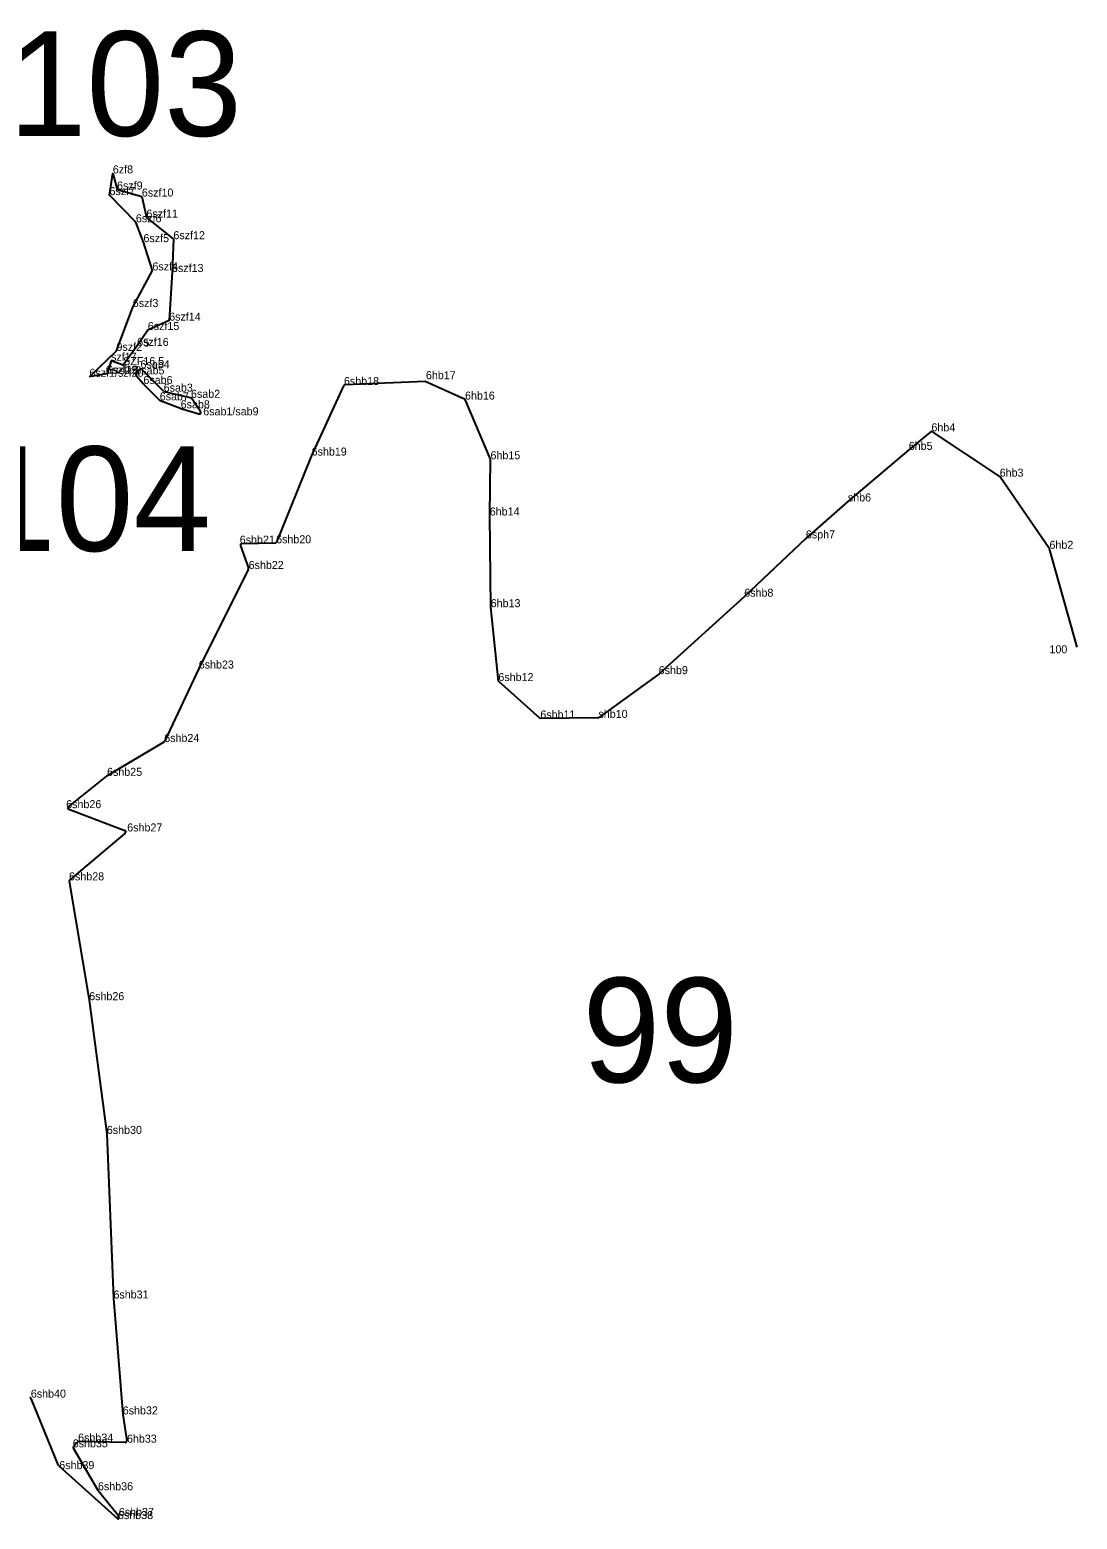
# Model space of a CAD drawing. Extents: x 2072529 to 2268812, y 436423 to 470008.
# Drawn here: x 2138755 to 2139410, y 443063 to 443993 of the extents above; entities that cross this region are included whole.
import ezdxf

# ---------------------------------------------------------------- set-up
doc = ezdxf.new("R2010")
doc.units = 0
for name, color, linetype in [('Old_Level_10', 7, 'Continuous'), ('Old_Level_20', 7, 'Continuous'), ('Old_Level_60', 7, 'Continuous'), ('Old_Level_62', 7, 'Continuous')]:
    doc.layers.add(name, color=color, linetype=linetype)

msp = doc.modelspace()

# ---------------------------------------------------------------- linework, layer by layer
at = {"layer": 'Old_Level_10'}
for p, q in [((2138823.896, 443781.131), (2138821.883, 443778.794)), ((2138838.864, 443767.558), (2138825.364, 443781.182)), ((2138821.875, 443777.498), (2138826.367, 443772.158)), ((2138826.425, 443772.095), (2138836.453, 443762.059)), ((2138951.494, 443770.917), (2138931.546, 443727.436)), ((2138951.494, 443770.917), (2138931.546, 443727.436)), ((2138951.494, 443770.917), (2138931.546, 443727.436)), ((2139002.527, 443773.731), (2138952.359, 443771.499)), ((2139002.527, 443773.731), (2138952.359, 443771.499)), ((2139002.527, 443773.731), (2138952.359, 443771.499)), ((2138836.804, 443761.831), (2138849.667, 443756.932)), ((2138855.768, 443763.565), (2138839.353, 443767.287)), ((2138862.122, 443754.921), (2138856.366, 443763.162)), ((2138849.725, 443756.912), (2138861.004, 443753.394)), ((2138931.529, 443727.395), (2138909.575, 443673.234)), ((2138931.529, 443727.395), (2138909.575, 443673.234)), ((2138931.529, 443727.395), (2138909.575, 443673.234)), ((2138887.055, 443671.027), (2138892.018, 443656.954)), ((2138887.055, 443671.027), (2138892.018, 443656.954)), ((2138887.055, 443671.027), (2138892.018, 443656.954)), ((2138908.66, 443672.61), (2138887.986, 443672.36)), ((2138908.66, 443672.61), (2138887.986, 443672.36)), ((2138908.66, 443672.61), (2138887.986, 443672.36)), ((2138891.969, 443656.173), (2138861.016, 443594.36)), ((2138891.969, 443656.173), (2138861.016, 443594.36)), ((2138891.969, 443656.173), (2138861.016, 443594.36)), ((2138861.006, 443594.338), (2138839.528, 443548.761)), ((2138861.006, 443594.338), (2138839.528, 443548.761)), ((2138861.006, 443594.338), (2138839.528, 443548.761)), ((2138839.133, 443548.327), (2138803.723, 443527.353)), ((2138839.133, 443548.327), (2138803.723, 443527.353)), ((2138839.133, 443548.327), (2138803.723, 443527.353)), ((2138803.612, 443527.277), (2138779.509, 443508.203)), ((2138803.612, 443527.277), (2138779.509, 443508.203)), ((2138803.612, 443527.277), (2138779.509, 443508.203)), ((2138779.774, 443506.484), (2138814.695, 443493.167)), ((2138779.774, 443506.484), (2138814.695, 443493.167)), ((2138779.774, 443506.484), (2138814.695, 443493.167)), ((2138814.982, 443491.467), (2138780.361, 443462.361)), ((2138814.982, 443491.467), (2138780.361, 443462.361)), ((2138814.982, 443491.467), (2138780.361, 443462.361)), ((2138780.019, 443461.429), (2138792.508, 443387.166)), ((2138780.019, 443461.429), (2138792.508, 443387.166)), ((2138780.019, 443461.429), (2138792.508, 443387.166)), ((2138792.513, 443387.131), (2138803.533, 443303.65)), ((2138792.513, 443387.131), (2138803.533, 443303.65)), ((2138792.513, 443387.131), (2138803.533, 443303.65)), ((2138803.541, 443303.56), (2138807.688, 443200.784)), ((2138803.541, 443303.56), (2138807.688, 443200.784)), ((2138803.541, 443303.56), (2138807.688, 443200.784)), ((2138807.691, 443200.744), (2138813.489, 443128.377)), ((2138807.691, 443200.744), (2138813.489, 443128.377)), ((2138807.691, 443200.744), (2138813.489, 443128.377)), ((2138773.409, 443096.375), (2138756.294, 443138.223)), ((2138773.409, 443096.375), (2138756.294, 443138.223)), ((2138773.409, 443096.375), (2138756.294, 443138.223)), ((2138813.497, 443128.309), (2138815.947, 443111.862)), ((2138813.497, 443128.309), (2138815.947, 443111.862)), ((2138813.497, 443128.309), (2138815.947, 443111.862)), ((2138785.286, 443111.026), (2138782.751, 443108.342)), ((2138785.286, 443111.026), (2138782.751, 443108.342)), ((2138785.286, 443111.026), (2138782.751, 443108.342)), ((2138814.937, 443110.715), (2138786.035, 443111.339)), ((2138814.937, 443110.715), (2138786.035, 443111.339)), ((2138814.937, 443110.715), (2138786.035, 443111.339)), ((2138782.616, 443107.149), (2138797.969, 443081.018)), ((2138782.616, 443107.149), (2138797.969, 443081.018)), ((2138782.616, 443107.149), (2138797.969, 443081.018)), ((2138798.055, 443080.894), (2138810.724, 443065.303)), ((2138798.055, 443080.894), (2138810.724, 443065.303)), ((2138798.055, 443080.894), (2138810.724, 443065.303))]:
    msp.add_line(p, q, dxfattribs=at)
for points in [[(2138792.642, 443776.631), (2138809.577, 443792.835), (2138819.756, 443820.198), (2138832.026, 443843.086), (2138826.433, 443860.763), (2138821.712, 443873.142), (2138805.205, 443890.138), (2138807.288, 443903.696), (2138809.923, 443893.609), (2138825.434, 443889.222), (2138828.265, 443876.068), (2138845.15, 443862.59), (2138844.269, 443842.118), (2138842.509, 443811.724), (2138829.148, 443805.847), (2138822.46, 443795.913), (2138813.774, 443783.941), (2138806.17, 443786.61), (2138803.714, 443778.547)], [(2138803.714, 443778.547), (2138802.854, 443778.531), (2138792.642, 443776.631)], [(2139410.009, 443607.766), (2139392.664, 443669.159), (2139361.562, 443714.226), (2139318.899, 443742.545), (2139304.732, 443730.955), (2139266.654, 443698.735), (2139240.447, 443675.675), (2139201.894, 443639.24), (2139148.446, 443590.849), (2139110.796, 443563.488), (2139074.459, 443563.129), (2139048.251, 443586.516), (2139043.449, 443632.681), (2139042.868, 443689.962), (2139043.348, 443725.089), (2139027.398, 443762.38), (2139002.527, 443773.731)], [(2138810.914, 443064.414), (2138810.52, 443062.939), (2138773.667, 443096.01)], [(2138810.914, 443064.414), (2138810.52, 443062.939), (2138773.667, 443096.01)], [(2138810.914, 443064.414), (2138810.52, 443062.939), (2138773.667, 443096.01)]]:
    msp.add_lwpolyline(points, dxfattribs=at)
for centre, start, end in [((2138824.653, 443780.478), 44.737836, 139.258758), ((2138822.64, 443778.141), 139.258761, 220.073953), ((2138827.133, 443772.802), 220.07395, 224.974756), ((2138952.403, 443770.5), 92.547281, 155.3553), ((2138952.403, 443770.5), 92.547281, 155.3553), ((2138952.403, 443770.5), 92.547281, 155.3553), ((2138837.16, 443762.765), 224.974756, 249.151003), ((2138839.574, 443768.262), 224.737836, 257.224161), ((2138855.547, 443762.589), 34.931606, 77.224161), ((2138850.023, 443757.866), 249.151003, 252.677678), ((2138861.302, 443754.349), 252.677678, 34.931608), ((2138932.455, 443727.019), 155.355303, 157.935158), ((2138932.455, 443727.019), 155.355303, 157.935158), ((2138932.455, 443727.019), 155.355303, 157.935158), ((2138887.998, 443671.36), 90.693039, 199.424089), ((2138887.998, 443671.36), 90.693039, 199.424089), ((2138887.998, 443671.36), 90.693039, 199.424089), ((2138908.648, 443673.61), 270.693039, 337.935158), ((2138908.648, 443673.61), 270.693039, 337.935158), ((2138908.648, 443673.61), 270.693039, 337.935158), ((2138891.075, 443656.621), 333.401061, 19.424089), ((2138891.075, 443656.621), 333.401061, 19.424089), ((2138891.075, 443656.621), 333.401061, 19.424089), ((2138861.911, 443593.912), 153.401064, 154.768203), ((2138861.911, 443593.912), 153.401064, 154.768203), ((2138861.911, 443593.912), 153.401064, 154.768203), ((2138838.623, 443549.187), 300.638183, 334.768203), ((2138838.623, 443549.187), 300.638183, 334.768203), ((2138838.623, 443549.187), 300.638183, 334.768203), ((2138804.233, 443526.493), 120.638183, 128.357542), ((2138804.233, 443526.493), 120.638183, 128.357542), ((2138804.233, 443526.493), 120.638183, 128.357542), ((2138780.13, 443507.419), 128.357542, 249.125186), ((2138780.13, 443507.419), 128.357542, 249.125186), ((2138780.13, 443507.419), 128.357542, 249.125186), ((2138814.338, 443492.232), 310.054678, 69.125186), ((2138814.338, 443492.232), 310.054678, 69.125186), ((2138814.338, 443492.232), 310.054678, 69.125186), ((2138781.005, 443461.595), 130.054678, 189.546467), ((2138781.005, 443461.595), 130.054678, 189.546467), ((2138781.005, 443461.595), 130.054678, 189.546467), ((2138791.522, 443387.001), 7.5197, 9.546469), ((2138791.522, 443387.001), 7.5197, 9.546469), ((2138791.522, 443387.001), 7.5197, 9.546469), ((2138802.542, 443303.519), 2.310836, 7.5197), ((2138802.542, 443303.519), 2.310836, 7.5197), ((2138802.542, 443303.519), 2.310836, 7.5197), ((2138808.687, 443200.824), 182.310833, 184.581247), ((2138808.687, 443200.824), 182.310833, 184.581247), ((2138808.687, 443200.824), 182.310833, 184.581247), ((2138755.369, 443137.845), 22.243586, 89.155339), ((2138755.369, 443137.845), 22.243586, 89.155339), ((2138755.369, 443137.845), 22.243586, 89.155339), ((2138814.486, 443128.457), 184.581247, 188.473306), ((2138814.486, 443128.457), 184.581247, 188.473306), ((2138814.486, 443128.457), 184.581247, 188.473306), ((2138786.013, 443110.34), 88.761608, 136.641786), ((2138786.013, 443110.34), 88.761608, 136.641786), ((2138786.013, 443110.34), 88.761608, 136.641786), ((2138814.958, 443111.714), 268.761608, 8.473306), ((2138814.958, 443111.714), 268.761608, 8.473306), ((2138814.958, 443111.714), 268.761608, 8.473306), ((2138783.478, 443107.655), 136.641786, 210.435406), ((2138783.478, 443107.655), 136.641786, 210.435406), ((2138783.478, 443107.655), 136.641786, 210.435406), ((2138774.335, 443096.754), 202.243586, 228.096344), ((2138774.335, 443096.754), 202.243586, 228.096344), ((2138774.335, 443096.754), 202.243586, 228.096344), ((2138798.831, 443081.525), 210.435406, 219.097353), ((2138798.831, 443081.525), 210.435406, 219.097353), ((2138798.831, 443081.525), 210.435406, 219.097353), ((2138809.948, 443064.672), 345.035969, 39.097353), ((2138809.948, 443064.672), 345.035969, 39.097353), ((2138809.948, 443064.672), 345.035969, 39.097353)]:
    msp.add_arc(centre, 1, start, end, dxfattribs=at)
at = {"layer": 'Old_Level_20'}
for p, q in [((2138807.288, 443903.696), (2138807.288, 443903.696)), ((2138809.923, 443893.609), (2138809.923, 443893.609)), ((2138805.205, 443890.138), (2138805.205, 443890.138)), ((2138825.434, 443889.222), (2138825.434, 443889.222)), ((2138821.712, 443873.142), (2138821.712, 443873.142)), ((2138828.265, 443876.068), (2138828.265, 443876.068)), ((2138826.433, 443860.763), (2138826.433, 443860.763)), ((2138845.15, 443862.59), (2138845.15, 443862.59)), ((2138832.026, 443843.086), (2138832.026, 443843.086)), ((2138844.269, 443842.118), (2138844.269, 443842.118)), ((2138819.756, 443820.198), (2138819.756, 443820.198)), ((2138842.509, 443811.724), (2138842.509, 443811.724)), ((2138829.148, 443805.847), (2138829.148, 443805.847)), ((2138809.577, 443792.835), (2138809.577, 443792.835)), ((2138822.46, 443795.913), (2138822.46, 443795.913)), ((2138806.17, 443786.61), (2138806.17, 443786.61)), ((2138813.774, 443783.941), (2138813.774, 443783.941)), ((2138824.602, 443781.951), (2138824.602, 443781.951)), ((2138792.642, 443776.631), (2138792.642, 443776.631)), ((2138802.854, 443778.531), (2138802.854, 443778.531)), ((2138821.327, 443778.149), (2138821.327, 443778.149)), ((2138826.395, 443772.125), (2138826.395, 443772.125)), ((2138951.749, 443771.472), (2138951.749, 443771.472)), ((2139002.256, 443774.066), (2139002.256, 443774.066)), ((2138836.604, 443761.907), (2138836.604, 443761.907)), ((2138839.069, 443767.351), (2138839.069, 443767.351)), ((2138856.145, 443763.479), (2138856.145, 443763.479)), ((2139027.398, 443762.38), (2139027.398, 443762.38)), ((2138849.696, 443756.921), (2138849.696, 443756.921)), ((2138863.797, 443752.523), (2138863.797, 443752.523)), ((2139318.899, 443742.545), (2139318.899, 443742.545)), ((2138931.537, 443727.416), (2138931.537, 443727.416)), ((2139043.348, 443725.089), (2139043.348, 443725.089)), ((2139304.732, 443730.955), (2139304.732, 443730.955)), ((2139361.562, 443714.226), (2139361.562, 443714.226)), ((2139266.654, 443698.735), (2139266.654, 443698.735)), ((2139042.868, 443689.962), (2139042.868, 443689.962)), ((2138886.591, 443672.343), (2138886.591, 443672.343)), ((2138909.325, 443672.618), (2138909.325, 443672.618)), ((2139240.447, 443675.675), (2139240.447, 443675.675)), ((2139392.664, 443669.159), (2139392.664, 443669.159)), ((2138892.159, 443656.553), (2138892.159, 443656.553)), ((2139043.449, 443632.681), (2139043.449, 443632.681)), ((2139201.894, 443639.24), (2139201.894, 443639.24)), ((2139409.048, 443607.286), (2139409.048, 443607.286)), ((2138861.011, 443594.349), (2138861.011, 443594.349)), ((2139048.251, 443586.516), (2139048.251, 443586.516)), ((2139148.446, 443590.849), (2139148.446, 443590.849)), ((2139074.459, 443563.129), (2139074.459, 443563.129)), ((2139110.796, 443563.488), (2139110.796, 443563.488)), ((2138839.397, 443548.483), (2138839.397, 443548.483)), ((2138803.665, 443527.319), (2138803.665, 443527.319)), ((2138778.13, 443507.111), (2138778.13, 443507.111)), ((2138816.283, 443492.561), (2138816.283, 443492.561)), ((2138779.924, 443461.993), (2138779.924, 443461.993)), ((2138792.511, 443387.149), (2138792.511, 443387.149)), ((2138803.539, 443303.605), (2138803.539, 443303.605)), ((2138807.689, 443200.764), (2138807.689, 443200.764)), ((2138756.044, 443138.835), (2138756.044, 443138.835)), ((2138813.492, 443128.343), (2138813.492, 443128.343)), ((2138785.591, 443111.349), (2138785.591, 443111.349)), ((2138816.122, 443110.689), (2138816.122, 443110.689)), ((2138782.236, 443107.796), (2138782.236, 443107.796)), ((2138773.496, 443096.163), (2138773.496, 443096.163)), ((2138773.816, 443094.169), (2138773.816, 443094.169)), ((2138773.816, 443094.169), (2138773.816, 443094.169)), ((2138797.77, 443080.29), (2138797.77, 443080.29)), ((2138797.77, 443080.29), (2138797.77, 443080.29)), ((2138798.007, 443080.953), (2138798.007, 443080.953)), ((2138810.52, 443062.939), (2138810.52, 443062.939)), ((2138811.046, 443064.907), (2138811.046, 443064.907))]:
    msp.add_line(p, q, dxfattribs=at)

# ---------------------------------------------------------------- texts
at = {"layer": 'Old_Level_60'}
for s, p in [('6zf8', (2138807.288, 443903.696)), ('6szf7', (2138805.205, 443890.138)), ('6szf9', (2138809.923, 443893.609)), ('6szf10', (2138825.434, 443889.222)), ('6szf6', (2138821.712, 443873.142)), ('6szf11', (2138828.265, 443876.068)), ('6szf5', (2138826.433, 443860.763)), ('6szf12', (2138845.15, 443862.59)), ('6szf4', (2138832.026, 443843.086)), ('6szf13', (2138844.269, 443842.118)), ('6szf3', (2138819.756, 443820.198)), ('6szf14', (2138842.509, 443811.724)), ('6szf15', (2138829.148, 443805.847)), ('9szf2', (2138809.577, 443792.835)), ('6szf16', (2138822.46, 443795.913)), ('5', (2138826.433, 443795.474)), ('szf17', (2138806.17, 443786.61)), ('SZF16.5', (2138813.774, 443783.941)), ('SZF16.5', (2138813.774, 443783.941)), ('6szf1/szf20', (2138792.642, 443776.631)), ('6szf1/szf20', (2138792.642, 443776.631)), ('6szf19', (2138802.854, 443778.531)), ('6szf18', (2138803.714, 443778.547)), ('6sab5', (2138821.327, 443778.149)), ('6sab4', (2138824.602, 443781.951)), ('6hb17', (2139002.964, 443775.128)), ('6sab6', (2138826.395, 443772.125)), ('6sab3', (2138839.069, 443767.351)), ('6shb18', (2138951.749, 443771.472)), ('6sab7', (2138836.604, 443761.907)), ('6sab8', (2138849.696, 443756.921)), ('6sab2', (2138856.145, 443763.479)), ('6hb16', (2139027.398, 443762.38)), ('6sab1/sab9', (2138863.797, 443752.523)), ('6hb4', (2139318.899, 443742.545)), ('6shb19', (2138931.537, 443727.416)), ('6hb5', (2139304.732, 443730.955)), ('6hb15', (2139043.348, 443725.089)), ('6hb3', (2139361.562, 443714.226)), ('shb6', (2139266.654, 443698.735)), ('6hb14', (2139042.868, 443689.962)), ('6shb21', (2138886.591, 443672.343)), ('6shb20', (2138909.325, 443672.618)), ('6sph7', (2139240.447, 443675.675)), ('6hb2', (2139392.664, 443669.159)), ('6shb22', (2138892.159, 443656.553)), ('6shb8', (2139201.894, 443639.24)), ('6hb13', (2139043.449, 443632.681)), ('100', (2139392.664, 443603.87)), ('6shb23', (2138861.011, 443594.349)), ('6shb9', (2139148.446, 443590.849)), ('6shb12', (2139048.251, 443586.516)), ('6shb11', (2139074.459, 443563.129)), ('shb10', (2139110.796, 443563.488)), ('6shb24', (2138839.397, 443548.483)), ('6shb25', (2138803.665, 443527.319)), ('6shb26', (2138778.13, 443507.111)), ('6shb27', (2138816.283, 443492.561)), ('6shb28', (2138779.924, 443461.993)), ('6shb26', (2138792.511, 443387.149)), ('6shb30', (2138803.539, 443303.605)), ('6shb31', (2138807.689, 443200.764)), ('6shb40', (2138756.044, 443138.835)), ('6shb32', (2138813.492, 443128.343)), ('6shb35', (2138782.236, 443107.796)), ('6shb34', (2138785.591, 443111.349)), ('6hb33', (2138816.122, 443110.689)), ('6shb39', (2138773.816, 443094.169)), ('6shb39', (2138773.816, 443094.169)), ('6shb36', (2138798.007, 443080.953)), ('6shb38', (2138810.52, 443062.939)), ('6shb37', (2138811.046, 443064.907))]:
    msp.add_text(s, height=5, dxfattribs=at).set_placement(p)
at = {"layer": 'Old_Level_62'}
for s, p in [('103', (2138742.207, 443927.104)), ('104', (2138722.99, 443667.752)), ('99', (2139100.82, 443335.8))]:
    msp.add_text(s, height=65.34, dxfattribs=at).set_placement(p)

doc.saveas('drawing.dxf')
